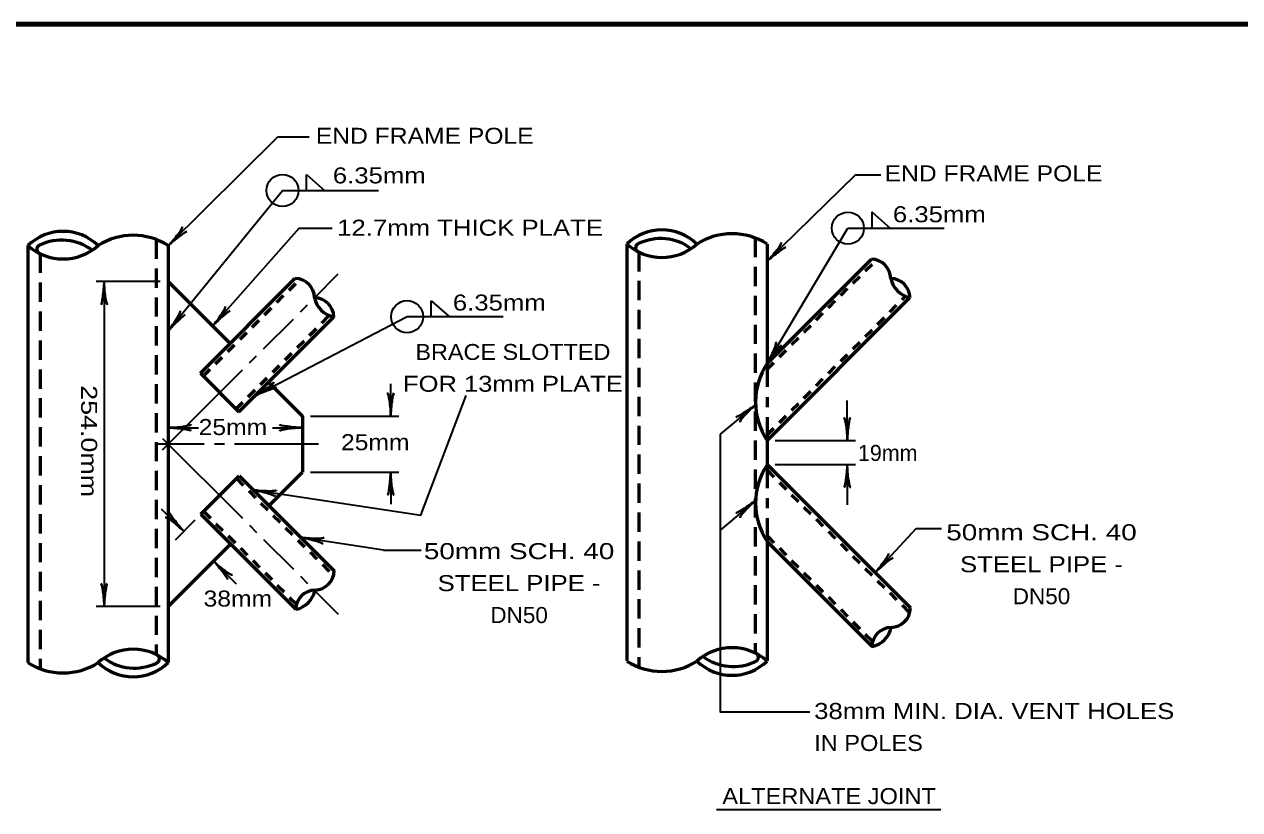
# Model space of a CAD drawing. Extents: x -29 to 827, y -14 to 530.
# Drawn here: x 457.6 to 641, y 404.8 to 523.3 of the extents above; entities that cross this region are included whole.
import ezdxf
from ezdxf.enums import TextEntityAlignment as Align

# ---------------------------------------------------------------- set-up
doc = ezdxf.new("R2010")
doc.units = 0
doc.header["$LTSCALE"] = 0.97
doc.linetypes.add('MEDIUM_DASHED', pattern=[4.5, 3, -1.5])
doc.linetypes.add('SHORT_DASHED', pattern=[2.7, 1.5, -1.2])
doc.layers.add('1', color=7, linetype='Continuous', lineweight=53)

msp = doc.modelspace()

# ---------------------------------------------------------------- linework, layer by layer
at = {"layer": '1', "lineweight": 35}
for p, q in [((500.2345, 498.1978), (500.2345, 500.6218)), ((500.2345, 500.6218), (502.9465, 498.1978)), ((479.3545, 477.0298), (496.6105, 498.1978)), ((496.6105, 498.1978), (511.1065, 498.1978)), ((569.7263, 472.083), (581.9183, 492.507)), ((581.9183, 492.507), (596.4383, 492.507)), ((478.1545, 484.4458), (468.4825, 484.4458)), ((469.6825, 484.4458), (469.6825, 435.4378)), ((501.4345, 482.0218), (505.0105, 485.5978)), ((499.2985, 479.8858), (500.3785, 480.9658)), ((519.0265, 479.1658), (519.0265, 481.5658)), ((519.0265, 481.5658), (521.7385, 479.1658)), ((492.4345, 467.2378), (515.4025, 479.1658)), ((493.7545, 474.3178), (498.2425, 478.8058)), ((515.4025, 479.1658), (529.8985, 479.1658)), ((491.5945, 472.1818), (492.6745, 473.2618)), ((478.5145, 459.0778), (490.5385, 471.1258)), ((512.9305, 464.1658), (512.9305, 469.0138)), ((581.8223, 460.491), (581.8223, 466.539)), ((500.8345, 464.1658), (514.1305, 464.1658)), ((567.9983, 465.867), (562.6223, 461.451)), ((479.3545, 462.4138), (483.9279, 462.4138)), ((495.1139, 462.4138), (499.6105, 462.4138)), ((478.5145, 460.8058), (490.5385, 448.7578)), ((570.9503, 460.491), (583.0463, 460.491)), ((484.8025, 459.9418), (477.5545, 459.9418)), ((487.8265, 459.9418), (486.3145, 459.9418)), ((502.0345, 459.9418), (489.3385, 459.9418)), ((570.9503, 456.843), (583.0463, 456.843)), ((581.8223, 456.843), (581.8223, 450.795)), ((500.8345, 455.7178), (514.1305, 455.7178)), ((512.9305, 455.7178), (512.9305, 450.8698)), ((567.9983, 451.419), (562.6223, 446.979)), ((478.2985, 450.1978), (481.7065, 446.7898)), ((480.4345, 445.4938), (483.4345, 448.4938)), ((491.5945, 447.7018), (492.6745, 446.6218)), ((511.8265, 443.9338), (499.3719, 445.8764)), ((493.7545, 445.5658), (498.2425, 441.0538)), ((511.8265, 443.9338), (517.5385, 443.9338)), ((486.2185, 442.3018), (489.6265, 438.8698)), ((499.2985, 439.9978), (500.3785, 438.9178)), ((501.4345, 437.8618), (505.0105, 434.2858)), ((478.1545, 435.4378), (468.4825, 435.4378)), ((562.0943, 404.835), (595.9343, 404.835))]:
    msp.add_line(p, q, dxfattribs=at)
at = {"layer": '1'}
for p, q in [((458.1865, 489.8698), (458.1865, 426.9898)), ((479.3545, 489.8698), (479.3545, 426.9898)), ((548.5583, 490.107), (548.5583, 427.227)), ((569.7263, 490.107), (569.7263, 472.083)), ((569.7263, 472.083), (585.4703, 487.851)), ((479.3545, 484.4458), (488.6905, 475.1098)), ((484.2025, 470.6218), (498.5305, 484.9498)), ((569.7263, 460.491), (591.2783, 482.043)), ((490.0105, 464.8138), (504.3385, 479.1418)), ((569.7263, 472.083), (569.7263, 468.555)), ((484.2025, 470.6218), (490.0105, 464.8138)), ((494.4985, 469.3018), (499.6105, 464.1658)), ((569.7263, 467.043), (569.7263, 465.531)), ((499.6105, 464.1658), (499.6105, 455.7178)), ((569.7263, 464.019), (569.7263, 460.491)), ((569.7263, 456.843), (591.3743, 435.219)), ((569.7263, 456.843), (569.7263, 453.315)), ((484.2745, 449.3578), (490.0825, 455.1658)), ((490.0825, 455.1658), (504.4105, 440.8378)), ((494.5705, 450.6778), (499.6105, 455.7178)), ((569.7263, 451.803), (569.7263, 450.291)), ((484.2745, 449.3578), (498.6025, 435.0298)), ((569.7263, 448.779), (569.7263, 445.227)), ((479.3545, 435.4378), (488.7625, 444.8698)), ((569.7263, 445.227), (585.5663, 429.411)), ((569.7263, 445.227), (569.7263, 427.227))]:
    msp.add_line(p, q, dxfattribs=at)
at = {"layer": '1', "linetype": 'MEDIUM_DASHED'}
for p, q in [((477.5545, 490.8058), (477.5545, 428.1898)), ((567.9263, 491.043), (567.9263, 428.427)), ((460.0105, 488.6698), (460.0105, 426.0538)), ((550.3823, 488.907), (550.3823, 426.291))]:
    msp.add_line(p, q, dxfattribs=at)
at = {"layer": '1', "linetype": 'SHORT_DASHED'}
for p, q in [((569.7263, 471.243), (586.2143, 487.731)), ((484.6345, 470.1898), (499.2745, 484.8298)), ((569.7263, 461.331), (590.6303, 482.235)), ((489.5785, 465.2218), (503.6665, 479.3338)), ((569.7263, 456.003), (591.2543, 434.475)), ((489.6505, 454.7338), (504.2905, 440.0938)), ((484.7065, 449.7898), (498.6985, 435.7738)), ((569.7263, 446.091), (585.6623, 430.155))]:
    msp.add_line(p, q, dxfattribs=at)
at = {"layer": '1', "lineweight": 158}
msp.add_lwpolyline([(820.0407, 523.2545), (28.3407, 523.1545), (28.4407, -2.8455)], dxfattribs=at)
at = {"layer": '1', "lineweight": 35}
for points in [[(479.3545, 489.8698), (495.8905, 506.2858), (500.6425, 506.2858)], [(569.7263, 487.539), (583.0703, 500.547), (586.8863, 500.547)], [(585.5663, 492.507), (585.5663, 494.931), (588.2783, 492.507)], [(486.0505, 477.7498), (499.1065, 492.4858), (504.0985, 492.4858)], [(492.2231, 453.0252), (517.4511, 449.218), (524.3075, 467.2791)], [(562.6223, 461.451), (562.6223, 419.547), (576.1823, 419.547)], [(586.0223, 440.547), (592.2383, 447.195), (596.0543, 447.195)]]:
    msp.add_lwpolyline(points, dxfattribs=at)
at = {"layer": '1'}
msp.add_lwpolyline([(569.7263, 460.491), (569.7263, 458.667), (569.7263, 456.843)], dxfattribs=at)
at = {"layer": '1', "lineweight": 35}
for centre in [(496.6013, 498.1943), (581.927, 492.505), (515.3951, 479.1564)]:
    msp.add_circle(centre, 2.4192, dxfattribs=at)
at = {"layer": '1'}
for centre, radius, start, end in [((463.4825, 484.4404), 7.5874, 45.77548, 134.22453), ((553.8543, 484.6776), 7.5874, 45.77548, 134.22453), ((564.4383, 481.8905), 9.7799, 57.24064, 122.75936), ((463.4825, 495.8302), 7.9648, 228.36161, 311.63839), ((460.1799, 489.3087), 0.6673, 110.41349, 254.79699), ((463.2902, 483.0057), 7.6928, 53.28342, 115.75809), ((474.0665, 481.6533), 9.7799, 57.24064, 122.75936), ((553.8543, 496.0674), 7.9648, 228.36161, 311.63839), ((550.5517, 489.5459), 0.6673, 110.41349, 254.79699), ((553.662, 483.2429), 7.6928, 53.28342, 115.75809), ((585.3924, 484.8393), 3.0011, 1.62229, 88.3797), ((498.4418, 481.9384), 3.0011, 1.62229, 88.3797), ((588.3074, 481.9244), 3.0011, 1.62229, 88.3797), ((591.9547, 485.5953), 3.6251, 190.66794, 259.33007), ((501.3569, 479.0234), 3.0011, 1.62229, 88.3797), ((505.0042, 482.6944), 3.6251, 190.66794, 259.33007), ((578.5134, 466.286), 10.5288, 146.53236, 213.46763), ((578.5134, 451.0446), 10.5288, 146.53237, 213.46764), ((501.4152, 440.9151), 3.0011, 271.62229, 358.3797), ((501.5849, 434.9154), 3.0011, 91.6203, 178.37771), ((497.9376, 438.5863), 3.6251, 280.66993, 349.33206), ((588.3659, 435.2998), 3.0011, 271.62229, 358.3797), ((588.5356, 429.3001), 3.0011, 91.6203, 178.37771), ((584.8883, 432.9711), 3.6251, 280.66993, 349.33206), ((564.4383, 421.2632), 7.9648, 48.36161, 131.63839), ((474.0665, 421.026), 7.9648, 48.36161, 131.63839), ((474.2588, 433.8504), 7.6928, 233.28342, 295.75809), ((477.3691, 427.5474), 0.6673, 290.41349, 74.79699), ((564.6306, 434.0876), 7.6928, 233.28342, 295.75809), ((567.7409, 427.7846), 0.6673, 290.41349, 74.79699), ((463.4825, 435.2029), 9.7799, 237.24064, 302.75936), ((474.0665, 432.4157), 7.5874, 225.77548, 314.22453), ((553.8543, 435.4401), 9.7799, 237.24064, 302.75936), ((564.4383, 432.6529), 7.5874, 225.77548, 314.22453)]:
    msp.add_arc(centre, radius, start, end, dxfattribs=at)
at = {"layer": '1', "lineweight": 40}
for centre, major_axis, ratio, start_param, end_param in [((480.0598, 491.0447), (-1.3999, -1.6557), 0.122415, 0.89635335, 3.14159265), ((480.0598, 491.0447), (-1.3999, -1.6557), 0.122415, 0.89635335, 3.14159265), ((480.5007, 490.6509), (-1.6575, -1.346), 0.07063, 3.14071475, 5.41810995), ((480.5007, 490.6509), (-1.6575, -1.346), 0.07063, 3.14071475, 5.41810995), ((570.4408, 488.6909), (-1.413, -1.6446), 0.122415, 0.89635335, 3.14159265), ((570.4408, 488.6909), (-1.413, -1.6446), 0.122415, 0.89635335, 3.14159265), ((570.8786, 488.2936), (1.6681, 1.3328), 0.07063, 6.28230741, 8.55970261), ((570.8786, 488.2936), (1.6681, 1.3328), 0.07063, 6.28230741, 8.55970261), ((469.4257, 483.0788), (0.2125, 2.1246), 0.07063, 3.14071475, 5.41810995), ((470.0159, 483.1143), (-0.1889, 2.16), 0.122415, 0.89635335, 3.14159265), ((486.6703, 478.9571), (-1.2909, -1.742), 0.122415, 0.89635335, 3.14159265), ((486.6703, 478.9571), (-1.2909, -1.742), 0.122415, 0.89635335, 3.14159265), ((479.9328, 478.2548), (-1.2175, -1.7942), 0.122415, 0.89635335, 3.14159265), ((479.9328, 478.2548), (-1.2175, -1.7942), 0.122415, 0.89635335, 3.14159265), ((480.4128, 477.9096), (1.5063, 1.5133), 0.07063, 6.28230741, 8.55970261), ((480.4128, 477.9096), (1.5063, 1.5133), 0.07063, 6.28230741, 8.55970261), ((487.1356, 478.5923), (-1.5679, -1.4494), 0.07063, 3.14071475, 5.41810995), ((487.1356, 478.5923), (-1.5679, -1.4494), 0.07063, 3.14071475, 5.41810995), ((570.1204, 473.3967), (-0.9458, -1.9511), 0.122415, 0.89635335, 3.14159265), ((570.6452, 473.1244), (1.2721, 1.7149), 0.07063, 6.28230741, 8.55970261), ((493.4609, 468.1472), (-1.8301, -1.1628), 0.122415, 0.89635335, 3.14159265), ((493.4609, 468.1472), (-1.8301, -1.1628), 0.122415, 0.89635335, 3.14159265), ((493.7643, 467.6397), (-1.9836, -0.7903), 0.07063, 3.14071475, 5.41810995), ((493.7643, 467.6397), (-1.9836, -0.7903), 0.07063, 3.14071475, 5.41810995), ((512.5906, 465.4936), (0.1889, -2.16), 0.122415, 0.89635335, 3.14159265), ((513.1808, 465.529), (-0.2125, -2.1246), 0.07063, 3.14071475, 5.41810995), ((566.7852, 465.206), (-1.7725, -1.1905), 0.07063, 6.28230741, 8.55970261), ((566.7852, 465.206), (-1.7725, -1.1905), 0.07063, 6.28230741, 8.55970261), ((567.1886, 464.7738), (1.544, 1.5223), 0.122415, 0.89635335, 3.14159265), ((567.1886, 464.7738), (1.544, 1.5223), 0.122415, 0.89635335, 3.14159265), ((480.7138, 462.1542), (-2.1246, 0.2125), 0.07063, 3.14071475, 5.41810995), ((480.6784, 462.7444), (-2.16, -0.1889), 0.122415, 0.89635335, 3.14159265), ((498.2993, 462.076), (2.16, 0.1889), 0.122415, 0.89635335, 3.14159265), ((498.2639, 462.6661), (2.1246, -0.2125), 0.07063, 3.14071475, 5.41810995), ((581.492, 461.7996), (0.1889, -2.16), 0.122415, 0.89635335, 3.14159265), ((581.492, 461.7996), (0.1889, -2.16), 0.122415, 0.89635335, 3.14159265), ((582.0822, 461.835), (-0.2125, -2.1246), 0.07063, 3.14071475, 5.41810995), ((582.0822, 461.835), (-0.2125, -2.1246), 0.07063, 3.14071475, 5.41810995), ((581.5703, 455.4955), (0.2125, 2.1246), 0.07063, 3.14071475, 5.41810995), ((581.5703, 455.4955), (0.2125, 2.1246), 0.07063, 3.14071475, 5.41810995), ((582.1605, 455.531), (-0.1889, 2.16), 0.122415, 0.89635335, 3.14159265), ((582.1605, 455.531), (-0.1889, 2.16), 0.122415, 0.89635335, 3.14159265), ((512.6689, 454.3511), (0.2125, 2.1246), 0.07063, 3.14071475, 5.41810995), ((513.2591, 454.3866), (-0.1889, 2.16), 0.122415, 0.89635335, 3.14159265), ((493.5674, 453.1577), (-2.1468, 0.1345), 0.122415, 0.89635335, 3.14159265), ((493.5148, 452.5735), (2.0527, -0.5229), 0.07063, 6.28230741, 8.55970261), ((566.7839, 450.7557), (1.7725, 1.1905), 0.07063, 3.14071475, 5.41810995), ((566.7839, 450.7557), (1.7725, 1.1905), 0.07063, 3.14071475, 5.41810995), ((567.1873, 450.3236), (1.544, 1.5223), 0.122415, 0.89635335, 3.14159265), ((567.1873, 450.3236), (1.544, 1.5223), 0.122415, 0.89635335, 3.14159265), ((480.939, 447.9237), (-1.3521, 1.6525), 0.07063, 6.28230741, 8.55970261), ((480.5467, 447.4813), (1.6609, -1.3938), 0.122415, 0.89635335, 3.14159265), ((500.6613, 445.4183), (2.0501, -0.5331), 0.07063, 6.28230741, 8.55970261), ((500.7168, 446.0022), (-2.1461, 0.1451), 0.122415, 0.89635335, 3.14159265), ((486.9844, 441.1549), (1.3521, -1.6526), 0.07063, 6.28230741, 8.55970261), ((487.3767, 441.5972), (-1.6609, 1.3938), 0.122415, 0.89635335, 3.14159265), ((586.6815, 441.7497), (-1.3392, -1.7052), 0.122415, 0.89635335, 3.14159265), ((586.6815, 441.7497), (-1.3392, -1.7052), 0.122415, 0.89635335, 3.14159265), ((587.1363, 441.372), (1.6079, 1.4049), 0.07063, 6.28230741, 8.55970261), ((587.1363, 441.372), (1.6079, 1.4049), 0.07063, 6.28230741, 8.55970261), ((469.3474, 436.7656), (0.1889, -2.16), 0.122415, 0.89635335, 3.14159265), ((469.9376, 436.801), (-0.2125, -2.1246), 0.07063, 3.14071475, 5.41810995)]:
    msp.add_ellipse(centre, major_axis=major_axis, ratio=ratio, start_param=start_param, end_param=end_param, dxfattribs=at)

# ---------------------------------------------------------------- texts
at = {"layer": '1'}
for s, width, p in [('END FRAME POLE', 1.15, (501.6265, 505.2298)), ('6.35mm', 1.2, (504.195, 499.2586)), ('END FRAME POLE', 1.15, (587.4623, 499.563)), ('6.35mm', 1.2, (588.7117, 493.3978)), ('12.7mm THICK PLATE', 1.2, (504.8425, 491.3674)), ('6.35mm', 1.2, (522.3057, 480.0778)), ('25mm', 1.15, (483.9485, 461.3026)), ('25mm', 1.15, (505.4273, 459.0154)), ('38mm', 1.15, (484.6928, 435.433)), ('38mm MIN. DIA. VENT HOLES', 1.2, (576.8303, 418.4718)), ('IN POLES', 1.1, (576.8303, 413.6526))]:
    msp.add_text(s, height=2.419, dxfattribs=dict(at, width=width)).set_placement(p)
for s, height, width, p in [('BRACE SLOTTED', 2.4, 1.1, (531.3713, 472.6367)), ('FOR 13mm PLATE', 2.4, 1.2, (531.3712, 467.8367)), ('50mm SCH. 40', 2.419, 1.3, (611.1386, 445.4262)), ('50mm SCH. 40', 2.419, 1.3, (532.3037, 442.5846)), ('STEEL PIPE -', 2.419, 1.2, (611.1386, 440.607)), ('STEEL PIPE -', 2.419, 1.2, (532.3037, 437.7654)), ('DN50', 2.419, 1.05, (611.1386, 435.7878)), ('DN50', 2.419, 1.05, (532.3038, 432.9462)), ('ALTERNATE JOINT', 2.419, 1.1, (579.0864, 405.6393))]:
    msp.add_text(s, height=height, dxfattribs=dict(at, width=width)).set_placement(p, align=Align.CENTER)
at = {"layer": '1', "width": 1.25}
msp.add_text('254.0mm', height=2.419, rotation=270, dxfattribs=at).set_placement((466.2091, 468.8156))
at = {"layer": '1'}
msp.add_text('19mm', height=2.419, dxfattribs=at).set_placement((583.4392, 457.395))

doc.saveas('drawing.dxf')
